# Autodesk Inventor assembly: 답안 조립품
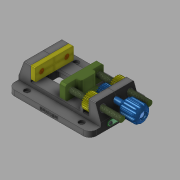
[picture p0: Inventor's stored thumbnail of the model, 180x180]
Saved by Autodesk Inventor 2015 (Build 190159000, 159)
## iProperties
Created: 2018-03
Part Number: 답안 조립품
Document SubType Name: Assembly
Designer: SCD-A03
Mass: 1443.92 g
Surface Area: 918.511 cm^2
Volume: 340.421 cm^3
Density: 4.24157 g/cm^3
Author: SCD-A03
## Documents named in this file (10)
- C:\Users\SCD-A03\Desktop\380308V1003\답안 조립품.iam
- C:\Users\SCD-A03\Desktop\380308V1003\바이스본체 A.ipt
- C:\Users\SCD-A03\Desktop\380308V1003\고정 플레이트.ipt
- C:\Users\SCD-A03\Desktop\380308V1003\바이스본체 B.ipt
- C:\Users\SCD-A03\Desktop\380308V1003\스퍼기어.ipt
- C:\Users\SCD-A03\Desktop\380308V1003\슬라이딩 부품.ipt
- C:\Users\SCD-A03\Desktop\380308V1003\십자오목머리나사 M3.ipt
- C:\Users\SCD-A03\Desktop\380308V1003\십자오목머리나사 M4.ipt
- C:\Users\SCD-A03\Desktop\380308V1003\지지대.ipt
- C:\Users\SCD-A03\Desktop\380308V1003\핸들.ipt
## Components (3 placed, 2 different names)
1. 고정 플레이트:1
2. 핸들:1 — 구동부
3. 고정 플레이트:2
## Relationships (1: Angle 1)
- 구동부 [Angle]: 핸들:1
